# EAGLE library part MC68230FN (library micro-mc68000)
68xxx PROCESSOR
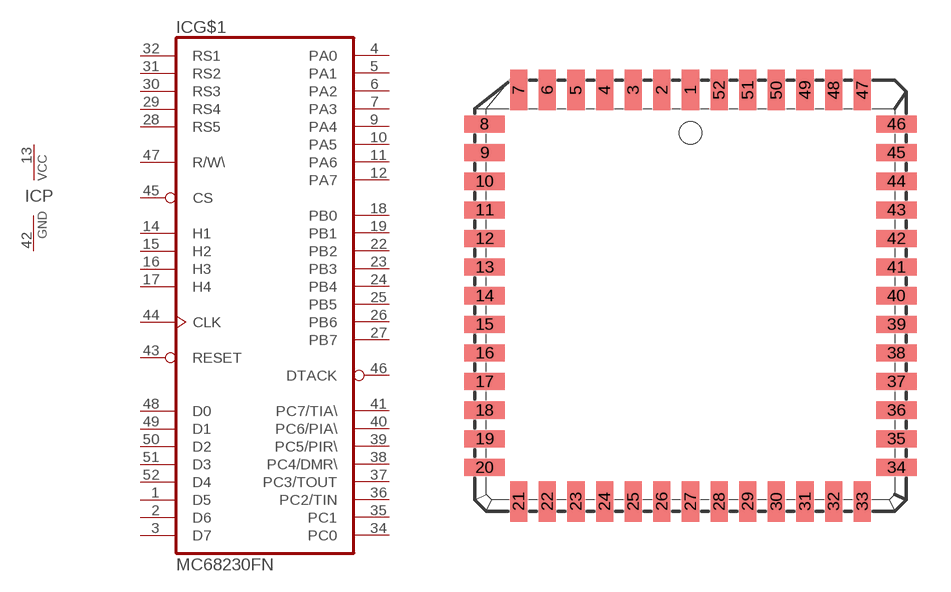
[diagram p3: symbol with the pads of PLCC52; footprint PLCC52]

Designator prefix IC; gates G$1=68230 P=PWRN

## MC68230FN  [PLCC52]
1  G$1:D5
2  G$1:D6
3  G$1:D7
4  G$1:PA0
5  G$1:PA1
6  G$1:PA2
7  G$1:PA3
9  G$1:PA4
10  G$1:PA5
11  G$1:PA6
12  G$1:PA7
13  P:VCC  pwr
14  G$1:H1  in
15  G$1:H2
16  G$1:H3  in
17  G$1:H4
18  G$1:PB0
19  G$1:PB1
22  G$1:PB2
23  G$1:PB3
24  G$1:PB4
25  G$1:PB5
26  G$1:PB6
27  G$1:PB7
28  G$1:RS5  in
29  G$1:RS4  in
30  G$1:RS3  in
31  G$1:RS2  in
32  G$1:RS1  in
34  G$1:PC0
35  G$1:PC1
36  G$1:PC2/TIN
37  G$1:PC3/TOUT
38  G$1:PC4/DMR\
39  G$1:PC5/PIR\
40  G$1:PC6/PIA\
41  G$1:PC7/TIA\
42  P:GND  pwr
43  G$1:RESET  in
44  G$1:CLK  in
45  G$1:CS  in
46  G$1:DTACK  out
47  G$1:R/W\  in
48  G$1:D0
49  G$1:D1
50  G$1:D2
51  G$1:D3
52  G$1:D4

## Footprint PLCC52 (pad centres in mm)
PLASTIC LEADED CHIP CARRIER square
smd 0.76 x 1.8: 1 0,9.13; 2 -1.27,9.13; 3 -2.54,9.13; 4 -3.81,9.13; 5 -5.08,9.13; 6 -6.35,9.13; 7 -7.62,9.13; 21 -7.62,-9.13; 22 -6.35,-9.13; 23 -5.08,-9.13; 24 -3.81,-9.13; 25 -2.54,-9.13; 26 -1.27,-9.13; 27 0,-9.13; 28 1.27,-9.13; 29 2.54,-9.13; 30 3.81,-9.13; 31 5.08,-9.13; 32 6.35,-9.13; 33 7.62,-9.13; 47 7.62,9.13; 48 6.35,9.13; 49 5.08,9.13; 50 3.81,9.13; 51 2.54,9.13; 52 1.27,9.13
smd 1.8 x 0.76: 8 -9.13,7.62; 9 -9.13,6.35; 10 -9.13,5.08; 11 -9.13,3.81; 12 -9.13,2.54; 13 -9.13,1.27; 14 -9.13,0; 15 -9.13,-1.27; 16 -9.13,-2.54; 17 -9.13,-3.81; 18 -9.13,-5.08; 19 -9.13,-6.35; 20 -9.13,-7.62; 34 9.13,-7.62; 35 9.13,-6.35; 36 9.13,-5.08; 37 9.13,-3.81; 38 9.13,-2.54; 39 9.13,-1.27; 40 9.13,0; 41 9.13,1.27; 42 9.13,2.54; 43 9.13,3.81; 44 9.13,5.08; 45 9.13,6.35; 46 9.13,7.62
